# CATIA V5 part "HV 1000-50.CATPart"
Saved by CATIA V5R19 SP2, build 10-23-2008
Part number: HV 1000-50
Bounding box of the stored display mesh (mm): x -24.865 to 24.865, y -24.997 to 24.997, z 0 to 157
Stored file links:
  C:\Users\Bora\Desktop\3D KATI MODEL- CATIA PART\HV serisi\HV 1000\HV 1000-50.CATPart
  C:\Program Files\Dassault Systemes\B19\intel_a\reffiles\standard\MetricThickPitch.txt
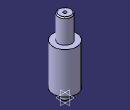
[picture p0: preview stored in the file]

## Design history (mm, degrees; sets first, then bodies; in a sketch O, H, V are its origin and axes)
Body1 (main body)
  Sketch1 on yz-plane, origin (0, 0, 0), H (0, 1, 0), V (0, 0, 1)
    point P1 (14, 155)
    point P3 (14, 155)
    point P8 (8, 17)
    point P10 (8, 1)
    point P11 (8, 17)
    point P12 (8, 1)
    arc A1 centre (12, 155) radius 2 from (14, 155) to (12, 157) ccw
    line L1 (14, 155) -> (14, 106)
    arc A2 centre (8, 18) radius 1 from (8, 19) to (8, 17) ccw
    line L2 (7, 0) -> (8, 1)
    line L3 (8, 17) -> (8, 1)
    line L4 (0, 0) -> (7, 0)
    line L5 (8, 19) -> (25, 19)
    line L6 (14, 106) -> (25, 106)
    line L7 (12, 157) -> (0, 157)
    point P13 (0, 157)
    line L8 (25, 106) -> (25, 19)
    horizontal: L4 H, L6 H
    tangency: L5 A2, L7 A1
    coincidence: P13 V, P1 P3, P8 P11, P10 P12
    vertical: L8 V
  Shaft1: profile Sketch1, axis Sketch1.V, angle 360
  Sketch2 on face of Shaft1 from Sketch1.L4, origin (0, 0, 0), H (1, 0, 0), V (0, -1, 0)
    point P1 (0, 0)
  Hole1: placed by Sketch2, at (0, 0, 0) direction (0, 0, 1), diameter 13.835, depth 19, threaded "M16", thread diameter 16, thread depth 19, pitch 2
  Sketch3 on face of Shaft1 from Sketch1.L7, origin (0, 0, 157), H (1, 0, 0), V (0, 1, 0)
    point P1 (0, 0)
  Hole2: placed by Sketch3, at (0, 0, 157) direction (0, 0, -1), diameter 6.647, depth 15, threaded "M8", thread diameter 8, thread depth 15, pitch 1.25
